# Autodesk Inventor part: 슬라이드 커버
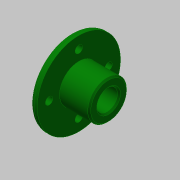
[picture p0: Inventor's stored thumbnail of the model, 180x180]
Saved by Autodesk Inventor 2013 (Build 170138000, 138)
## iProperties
Created: 2015-12
Part Number: 슬라이드 커버
Document SubType Name: Modeling
Designer: mdu
Density: 2.71 g/cm^3
Material: 알루미늄 6061
Author: mdu
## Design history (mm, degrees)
sketch "스케치1"
  geometry: L1 (-12.5, 0)-(12.5, 0); L2 (-12.5, 0)-(-12.5, 28); L3 (-12.5, 28)-(-7.5, 28); L4 (-7.5, 28)-(-7.5, 13); L5 (-7.5, 13)-(12.5, 13); L6 (12.5, 13)-(12.5, 0); 2 further points
  constraints: 12 end point, 3 perpendicular, 1 coincident, 1 horizontal, 1 midpoint, 1 parallel
  dimensions: "d1" = 56 diameter of L3 L1; "d2" = 26 diameter of L5 L1; "d5" = 5 distance of L2.end L3.end; "d32" = 20 distance of L4.end L5.end
revolve "회전1" sketch "스케치1" stored, may be unused: angle "d6" = 90 deg
sketch "스케치2" dims "d33" = 40
  geometry: 3 further points
  constraints: 2 vertical alignment, 1 coincident, 2 other
hole "구멍1" sketch "스케치2" at (0, 20) diameter "d8" = 5; stored, may be unused: countersink angle "d12" = 90 deg, drill point angle "d14" = 118 deg; dims "d9" = 6, "d10" = 8, "d11" = 4.4, "d13" = 8
hole "구멍2" diameter "d20" = 14; stored, may be unused: countersink angle "d24" = 90 deg, drill point angle "d26" = 0 deg; dims "d18" = 10, "d19" = 10, "d21" = 6, "d22" = 8, "d23" = 4.4, "d25" = 8
fillet "모깎기1" dims "d27" = 3
chamfer "모따기1" distance "d29" = 1; stored, may be unused: second distance "d30" = 2, angle "d31" = 45 deg
node "솔리드1"
pattern_circular "원형 패턴1" dims angle "d16" = 360 deg
